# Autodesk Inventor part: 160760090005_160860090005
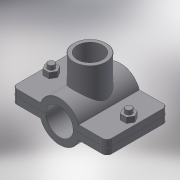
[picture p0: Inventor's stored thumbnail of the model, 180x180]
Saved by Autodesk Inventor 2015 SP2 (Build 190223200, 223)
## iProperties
Created: 2017-05
Part Number: 160760090005_160860090005
Material: Generic
Description: PLASSON SADDLE 90-1/2"
Document SubType Name: Modeling
Designer: KIM
Density: 1 g/cm^3
Appearance: Default
Author: KIM
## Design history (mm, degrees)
derived "16076.ipt"
feature "Solid1::16076.ipt"
feature "Solid2::16076.ipt"
tag "TaggingFeature1"
body "Solid1"
other parameters: "d0" = 99, "d1" = 141, "d2" = 45, "d4" = 105, "d5" = 0, "d6" = 7.05, "d7" = 141, "d8" = 0.1, "d10" = 0, "d11" = 0.9, "d14" = 24.2203, "d20" = 0.9, "d23" = 0.9, "d36" = 13, "d37" = 10.4, "d38" = 53, "d39" = 0, "d40" = 3, "d41" = 5, "d42" = 0, "d43" = 8, "d44" = 3, "d45" = 0, "d46" = 0.9, "d51" = 72, "d52" = 18.631, "d53" = 18, "d54" = 0, "d55" = 16, "d57" = 0, "d58" = 97.2, "d60" = 0, "d62" = 13, "d63" = 10.4, "d66" = 84.2, "B_" = 16, "G_" = 18.631, "A_" = 72, "L_" = 141, "L_1" = 105, "l_2" = 18
